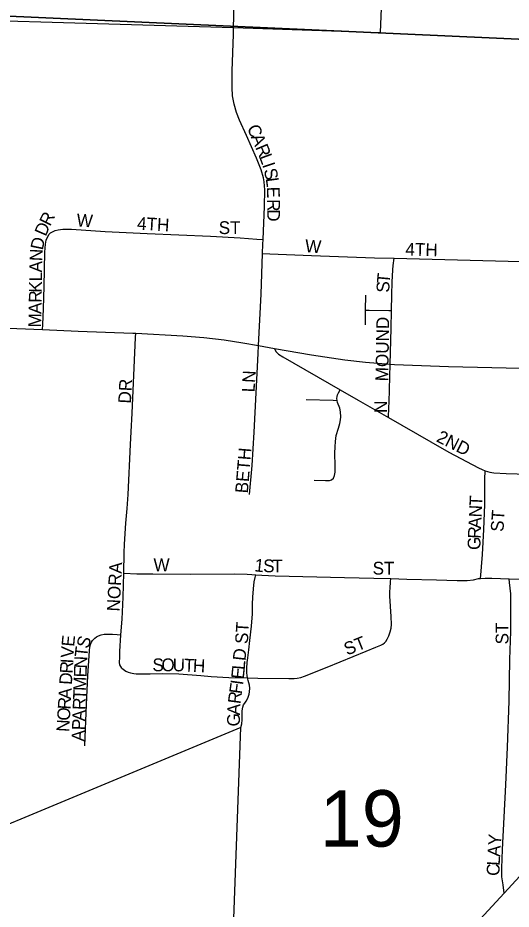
# Model space of a CAD drawing. Extents: x 0 to 34, y 0 to 22.
# Drawn here: x 24.458 to 24.824, y 14.523 to 15.184 of the extents above; entities that cross this region are included whole.
import ezdxf

# ---------------------------------------------------------------- set-up
doc = ezdxf.new("R2010")
doc.units = 0
for name, color, linetype in [('GM_X_City_Street', 7, 'Continuous'), ('GM_X_City_Street_Text', 7, 'Continuous'), ('GM_X_Corporation', 7, 'Continuous'), ('GM_X_County_Road', 7, 'Continuous'), ('GM_X_Section', 7, 'Continuous'), ('GM_X_Section_Text', 7, 'Continuous')]:
    doc.layers.add(name, color=color, linetype=linetype)

msp = doc.modelspace()

# ---------------------------------------------------------------- linework, layer by layer
at = {"layer": 'GM_X_City_Street'}
for points in [[(24.63967, 15.01998), (24.64075, 15.04448), (24.64086, 15.05679), (24.64034, 15.06286), (24.63984, 15.06586), (24.63824, 15.0717), (24.63486, 15.08027), (24.62723, 15.09719), (24.62213, 15.10851), (24.61986, 15.11434), (24.61812, 15.12038), (24.61706, 15.12658), (24.61668, 15.13284), (24.61681, 15.14527), (24.61766, 15.17219), (24.61777, 15.17647)], [(24.47603, 14.95328), (24.47618, 14.95687), (24.47668, 14.96882), (24.47735, 14.98533), (24.47782, 15.01056), (24.47817, 15.01651), (24.47887, 15.0197), (24.47996, 15.02219), (24.48106, 15.02398)], [(24.48106, 15.02398), (24.48206, 15.02498), (24.48335, 15.02577), (24.48544, 15.02667), (24.48763, 15.02736), (24.4912, 15.02777), (24.49746, 15.02767), (24.52247, 15.02608), (24.55374, 15.02442), (24.60066, 15.02253), (24.62254, 15.02142), (24.63502, 15.02037), (24.63967, 15.01998)], [(24.63929, 15.00962), (24.63953, 15.01665), (24.63967, 15.01998)], [(24.63631, 14.94137), (24.63827, 14.97949), (24.63929, 15.00962)], [(24.63929, 15.00962), (24.64461, 15.00942), (24.67564, 15.00824), (24.72219, 15.00654), (24.73678, 15.00623)], [(24.73499, 14.96752), (24.73522, 14.9791), (24.7354, 14.98839), (24.73593, 14.99766), (24.73622, 15.00074), (24.73678, 15.00623)], [(24.73678, 15.00623), (24.82129, 15.00409), (24.86419, 15.00301), (24.89848, 15.00199)], [(24.71572, 14.96769), (24.71582, 14.97875)], [(24.71563, 14.95678), (24.71572, 14.96769)], [(24.71572, 14.96769), (24.71822, 14.96767), (24.7328, 14.96754), (24.73499, 14.96752)], [(24.73392, 14.92766), (24.73471, 14.95419), (24.73499, 14.96752)], [(24.31108, 14.95974), (24.31123, 14.95974), (24.34731, 14.95826), (24.41255, 14.95581), (24.47603, 14.95328)], [(24.47603, 14.95328), (24.50259, 14.95222), (24.54298, 14.95064), (24.5452, 14.95051)], [(24.53645, 14.77253), (24.53651, 14.78774), (24.53678, 14.7941), (24.53778, 14.80972), (24.53877, 14.82064), (24.53963, 14.83103), (24.54132, 14.86816), (24.54175, 14.87735), (24.54247, 14.89125), (24.54505, 14.94737), (24.5452, 14.95051)], [(24.5452, 14.95051), (24.58024, 14.94865), (24.59576, 14.94742), (24.61089, 14.94579), (24.62471, 14.94349), (24.63631, 14.94137)], [(24.62958, 14.83105), (24.63147, 14.85254), (24.63304, 14.87714), (24.63602, 14.93561), (24.63631, 14.94137)], [(24.63631, 14.94137), (24.64808, 14.93932)], [(24.64808, 14.93932), (24.64911, 14.93694), (24.65097, 14.93508), (24.65426, 14.93298), (24.69681, 14.9086)], [(24.64808, 14.93932), (24.67559, 14.93451), (24.70015, 14.93082), (24.71556, 14.92905), (24.73392, 14.92766)], [(24.73274, 14.88803), (24.73296, 14.89552), (24.73308, 14.89945), (24.73392, 14.92766)], [(24.73392, 14.92766), (24.7372, 14.9274), (24.77725, 14.92601), (24.85207, 14.92409), (24.89246, 14.92292), (24.89564, 14.92282)], [(24.69459, 14.90073), (24.6944, 14.90223), (24.69447, 14.90371), (24.69492, 14.905), (24.69558, 14.90625), (24.69681, 14.9086)], [(24.69681, 14.9086), (24.71021, 14.90092), (24.73274, 14.88803)], [(24.67152, 14.90146), (24.6915, 14.90086), (24.69459, 14.90073)], [(24.67748, 14.84156), (24.68598, 14.84141), (24.68892, 14.84135), (24.69045, 14.84193), (24.69176, 14.84312), (24.69268, 14.84496), (24.69308, 14.84759), (24.69302, 14.85231), (24.69292, 14.86173), (24.69299, 14.86645), (24.69327, 14.87019), (24.69395, 14.87464), (24.69563, 14.88012), (24.69653, 14.8836), (24.69711, 14.88624), (24.69729, 14.88862), (24.69703, 14.89231), (24.6965, 14.89494), (24.69492, 14.89915), (24.69459, 14.90073)], [(24.73274, 14.88803), (24.76405, 14.8701), (24.77747, 14.86235), (24.79931, 14.85071), (24.80209, 14.84945), (24.80431, 14.84864)], [(24.80096, 14.76877), (24.80133, 14.77413), (24.80154, 14.77722), (24.80227, 14.78647), (24.80286, 14.79572), (24.80331, 14.805), (24.80398, 14.82363), (24.80422, 14.84227), (24.80431, 14.84864)], [(24.80431, 14.84864), (24.80782, 14.84762), (24.81077, 14.84709), (24.81997, 14.8465), (24.89262, 14.84433)], [(24.53426, 14.72686), (24.53506, 14.73845), (24.53599, 14.75486), (24.53645, 14.77253)], [(24.53645, 14.77253), (24.54598, 14.77226), (24.55798, 14.77206), (24.58593, 14.77201), (24.61878, 14.77206), (24.62785, 14.77194), (24.63142, 14.77173), (24.63436, 14.77151)], [(24.62817, 14.69494), (24.62776, 14.69668), (24.62751, 14.69886), (24.62751, 14.70224), (24.62791, 14.70628), (24.62838, 14.70992), (24.62904, 14.71581), (24.6299, 14.72276), (24.63105, 14.73334), (24.63168, 14.74248), (24.63188, 14.74969), (24.63195, 14.75473), (24.63248, 14.76096), (24.63314, 14.76631), (24.63387, 14.76941), (24.63436, 14.77151)], [(24.63436, 14.77151), (24.63877, 14.7712), (24.64865, 14.77068), (24.70003, 14.76946), (24.72178, 14.76905), (24.73436, 14.76861)], [(24.73162, 14.72363), (24.73287, 14.7262), (24.73384, 14.72903), (24.73453, 14.73195), (24.73479, 14.73447), (24.73472, 14.7405), (24.73374, 14.75565), (24.73374, 14.75896), (24.73387, 14.76147), (24.7342, 14.76631), (24.73436, 14.76861)], [(24.73436, 14.76861), (24.74633, 14.7682), (24.76832, 14.76758), (24.78364, 14.76712), (24.79092, 14.76712), (24.79571, 14.76774), (24.79943, 14.76867), (24.80096, 14.76877)], [(24.80096, 14.76877), (24.80423, 14.76897), (24.80934, 14.76897), (24.82204, 14.76856)], [(24.81835, 14.53533), (24.81759, 14.54143), (24.81681, 14.54758), (24.8166, 14.55377), (24.81723, 14.56773), (24.81967, 14.61572), (24.82087, 14.64361), (24.82213, 14.67768), (24.82259, 14.70868), (24.82327, 14.72935), (24.82343, 14.74746), (24.82327, 14.75721), (24.82234, 14.76572), (24.82204, 14.76856)], [(24.82204, 14.76856), (24.88984, 14.76666)], [(24.50742, 14.64469), (24.50868, 14.67525), (24.50972, 14.69663), (24.51081, 14.71495), (24.51125, 14.71797), (24.51157, 14.71965), (24.51236, 14.72157), (24.51322, 14.72282), (24.51481, 14.72455), (24.5161, 14.72546), (24.51759, 14.72619), (24.51951, 14.72693), (24.52184, 14.72735), (24.5249, 14.72745), (24.52795, 14.72732), (24.53136, 14.72712), (24.53426, 14.72686)], [(24.535, 14.70224), (24.53407, 14.70343), (24.53348, 14.70462), (24.53321, 14.70641), (24.53328, 14.71038), (24.53341, 14.71449), (24.53426, 14.72686)], [(24.62817, 14.69494), (24.6358, 14.69478), (24.65882, 14.6945), (24.66266, 14.69463), (24.66491, 14.69483), (24.66762, 14.69536), (24.67047, 14.69622), (24.68705, 14.70282), (24.71613, 14.71481), (24.72321, 14.71766), (24.72685, 14.71925), (24.72837, 14.72011), (24.72957, 14.7209), (24.73062, 14.72197), (24.73162, 14.72363)], [(24.535, 14.70224), (24.53678, 14.70072), (24.53797, 14.69999), (24.53963, 14.69926), (24.54135, 14.69867), (24.54373, 14.69814), (24.54559, 14.69807), (24.54883, 14.69801), (24.55578, 14.69807), (24.56471, 14.69827), (24.57728, 14.69794), (24.5935, 14.69668), (24.60117, 14.69609), (24.61421, 14.69523), (24.62817, 14.69494)], [(24.62302, 14.65816), (24.62387, 14.66101), (24.62414, 14.66399), (24.62401, 14.66776), (24.62414, 14.67054), (24.62454, 14.67319), (24.62513, 14.67491), (24.62599, 14.6763), (24.62705, 14.67782), (24.62831, 14.68007), (24.62923, 14.68292), (24.62956, 14.6847), (24.6297, 14.68749), (24.62956, 14.68954), (24.62917, 14.69126), (24.62859, 14.69304), (24.62817, 14.69494)], [(24.81835, 14.53533), (24.84462, 14.56383), (24.86375, 14.5843), (24.87205, 14.59355), (24.87803, 14.60069), (24.88178, 14.60597), (24.88395, 14.61046)], [(24.69894, 14.40751), (24.70034, 14.40903), (24.75754, 14.47027), (24.79182, 14.50653), (24.81835, 14.53533)]]:
    msp.add_lwpolyline(points, dxfattribs=at)
at = {"layer": 'GM_X_Corporation'}
msp.add_lwpolyline([(25.62787, 15.25304), (25.39901, 15.0362), (25.38711, 15.02549), (25.39055, 15.01962), (25.35642, 14.38899), (25.00223, 14.39963), (24.6145, 14.42219), (24.62302, 14.65816), (24.28934, 14.51924), (24.31045, 14.95945), (24.31458, 15.18617), (24.61779, 15.17724), (24.72674, 15.17362), (24.73507, 15.37828)], dxfattribs=at)
at = {"layer": 'GM_X_County_Road'}
msp.add_lwpolyline([(24.61777, 15.17647), (24.61802, 15.18617), (24.61842, 15.22031), (24.61833, 15.25447), (24.61898, 15.27622), (24.6202, 15.30727), (24.62131, 15.32898), (24.62124, 15.33822), (24.6205, 15.34429), (24.61908, 15.3502), (24.61811, 15.35308), (24.61562, 15.35863), (24.61243, 15.36379), (24.6106, 15.36621), (24.60639, 15.37055), (24.60163, 15.37432), (24.59653, 15.37775), (24.5825, 15.38561), (24.57958, 15.3873)], dxfattribs=at)
at = {"layer": 'GM_X_Section'}
for points in [[(24.14678, 15.53673), (24.15097, 15.53649), (24.644, 15.50874), (25.14407, 15.4826), (25.15684, 15.48182), (25.14694, 15.15424), (24.14401, 15.19968)], [(24.14401, 15.19968), (25.14694, 15.15424), (25.10789, 14.15143), (24.10202, 14.20337)]]:
    msp.add_lwpolyline(points, close=True, dxfattribs=at)

# ---------------------------------------------------------------- texts
at = {"layer": 'GM_X_City_Street_Text'}
for s, rotation, p in [('C', 292.81599, (24.62754, 15.10301)), ('A', 292.81829, (24.63044, 15.0961)), ('R', 292.71703, (24.63368, 15.08842)), ('L', 290.28424, (24.63653, 15.0816)), ('I', 288.36584, (24.63882, 15.07543)), ('S', 283.20142, (24.64007, 15.07169)), ('L', 277.50799, (24.64155, 15.06545)), ('E', 272.04932, (24.6424, 15.05907)), ('R', 270.12145, (24.64266, 15.05)), ('R', 63.65218, (24.48169, 15.02941)), ('W', 355.60387, (24.50103, 15.02992)), ('D', 270, (24.64267, 15.0425)), ('D', 66.60339, (24.47843, 15.02188)), ('4TH', 356.73129, (24.546, 15.02743)), ('ST', 0.00001, (24.60673, 15.0241)), ('D', 78.24864, (24.47624, 15.01179)), ('W', 355.84371, (24.67048, 15.01073)), ('4TH', 358.36431, (24.74511, 15.00826)), ('N', 87.33293, (24.4759, 15.00386)), ('A', 88.92896, (24.47574, 14.9956)), ('L', 88.93948, (24.47562, 14.98893)), ('T', 84.8575, (24.73339, 14.98709)), ('K', 88.92896, (24.47546, 14.9806)), ('S', 88.90721, (24.73327, 14.9806)), ('R', 88.93143, (24.47532, 14.9731)), ('A', 88.93434, (24.47517, 14.96477)), ('M', 88.92526, (24.47498, 14.95477)), ('MOUND', 89.05956, (24.73244, 14.91487)), ('LN', 86.98901, (24.63332, 14.90657)), ('DR', 86.98901, (24.54162, 14.89824)), ('N', 90, (24.73161, 14.89148)), ('2ND', 333.43131, (24.76752, 14.87058)), ('BETH', 85.36342, (24.62832, 14.83162)), ('T', 87.20049, (24.80207, 14.82216)), ('N', 87.2009, (24.80166, 14.81384)), ('ST', 86.42621, (24.81787, 14.80308)), ('A', 87.22273, (24.80126, 14.80552)), ('R', 87.49778, (24.80093, 14.79804)), ('G', 88.92896, (24.80078, 14.78977)), ('NORA', 87.06604, (24.53328, 14.74407)), ('W', 0.00001, (24.55839, 14.77409)), ('1', 353.77361, (24.6329, 14.77407)), ('S', 359.16616, (24.63966, 14.77338)), ('T', 359.85739, (24.64646, 14.77328)), ('ST', 0.00001, (24.72089, 14.7716)), ('ST', 86.42535, (24.62828, 14.71993)), ('ST', 90, (24.82161, 14.71982)), ('E', 84.8575, (24.49952, 14.7179)), ('S', 71.45271, (24.50985, 14.71613)), ('ST', 21.80392, (24.7019, 14.71147)), ('V', 86.62644, (24.49903, 14.70965)), ('T', 83.73219, (24.50924, 14.71002)), ('D', 83.64773, (24.6265, 14.70729)), ('I', 86.58731, (24.49878, 14.70549)), ('N', 87.76967, (24.50893, 14.70188)), ('S', 359.97268, (24.55756, 14.69993)), ('O', 359.95628, (24.56423, 14.69993)), ('U', 359.01638, (24.57252, 14.69992)), ('T', 357.62202, (24.58079, 14.69978)), ('H', 357.5076, (24.58744, 14.69951)), ('L', 85.67104, (24.626, 14.70073)), ('R', 86.62212, (24.49834, 14.698)), ('E', 88.03269, (24.5087, 14.69522)), ('E', 84.19766, (24.6253, 14.69383)), ('D', 86.62644, (24.49785, 14.68968)), ('M', 88.01439, (24.50836, 14.68523)), ('A', 86.61043, (24.4972, 14.67886)), ('F', 82.19054, (24.62379, 14.68274)), ('I', 82.22645, (24.6247, 14.68935)), ('T', 88.03269, (24.50813, 14.67857)), ('R', 82.59789, (24.62283, 14.67532)), ('R', 86.62897, (24.49677, 14.67138)), ('R', 88.00832, (24.50787, 14.67107)), ('A', 87.37659, (24.62246, 14.6672)), ('O', 86.61043, (24.49627, 14.66305)), ('A', 88.03368, (24.50758, 14.66274)), ('G', 89.84697, (24.62244, 14.65897)), ('N', 86.61043, (24.49578, 14.65474)), ('P', 88.00529, (24.50735, 14.65607)), ('A', 88.03258, (24.50706, 14.64774)), ('Y', 86.43482, (24.81597, 14.57046)), ('A', 86.43456, (24.81546, 14.56215)), ('L', 86.85653, (24.81509, 14.55551)), ('C', 88.8586, (24.81495, 14.5481))]:
    msp.add_text(s, height=0.00947, rotation=rotation, dxfattribs=at).set_placement(p)
at = {"layer": 'GM_X_Section_Text'}
msp.add_text('19', height=0.041856, rotation=0.00001, dxfattribs=at).set_placement((24.68173, 14.56987))

doc.saveas('drawing.dxf')
